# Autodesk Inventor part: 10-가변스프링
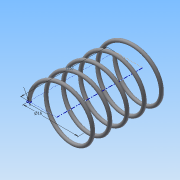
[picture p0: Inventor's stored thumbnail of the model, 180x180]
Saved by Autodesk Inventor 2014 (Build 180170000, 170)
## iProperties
Created: 2015-06
Part Number: 10-가변스프링
Material: 강철, 연강
Document SubType Name: Modeling
Designer: Administrator
Density: 7.86 g/cm^3
Appearance: 강철
Mass: 1.52996 g
Surface Area: 7.87153 cm^2
Volume: 0.194652 cm^3
Author: Administrator
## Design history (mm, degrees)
sketch "스케치1"
  geometry: L1 (0, 0)-(-8, 0); L2 (-8, 0)-(-8, 14.5); L3 (-8, 14.5)-(0, 14.5); L4 (0, 14.5)-(0, 0); C1 r 0.5 at (-8, 0)
  constraints: 8 end point, 2 parallel, 1 centre point, 1 coincident, 1 horizontal, 1 perpendicular
  dimensions: "d0" = 1 diameter of C1; "d1" = 16 diameter of L2 L4; "d2" = 14.5 distance of L1.end L2.end (derived)
feature "코일1" sketch "스케치1" pitch "d3" = 10; turns "d5" = 5; dims "d4" = 14.5 (= d2), "d6" = 0, angle "d7" = 90 deg, angle "d8" = 90 deg, "d9" = 0, "d10" = 0
sketch "스케치2"
  geometry: L1 (8.5, 0)-(7.5, 0) reference; 1 further point
  constraints: 1 horizontal alignment
extrude "돌출1" cut sketch "스케치2" stored distance "d11" = 10; taper "d12" = 0 deg
node "작업 평면1"
sketch "스케치3"
  geometry: L1 (7.5, 0)-(8.5, 0) reference; 1 further point
  constraints: 1 horizontal alignment
extrude "돌출2" cut sketch "스케치3" stored distance "d14" = 10; taper "d15" = 0 deg
node "솔리드1"
node "절단 모서리 투영1"
node "절단 모서리 투영2"
other parameters: "d13" = 14.5 (= d2)
